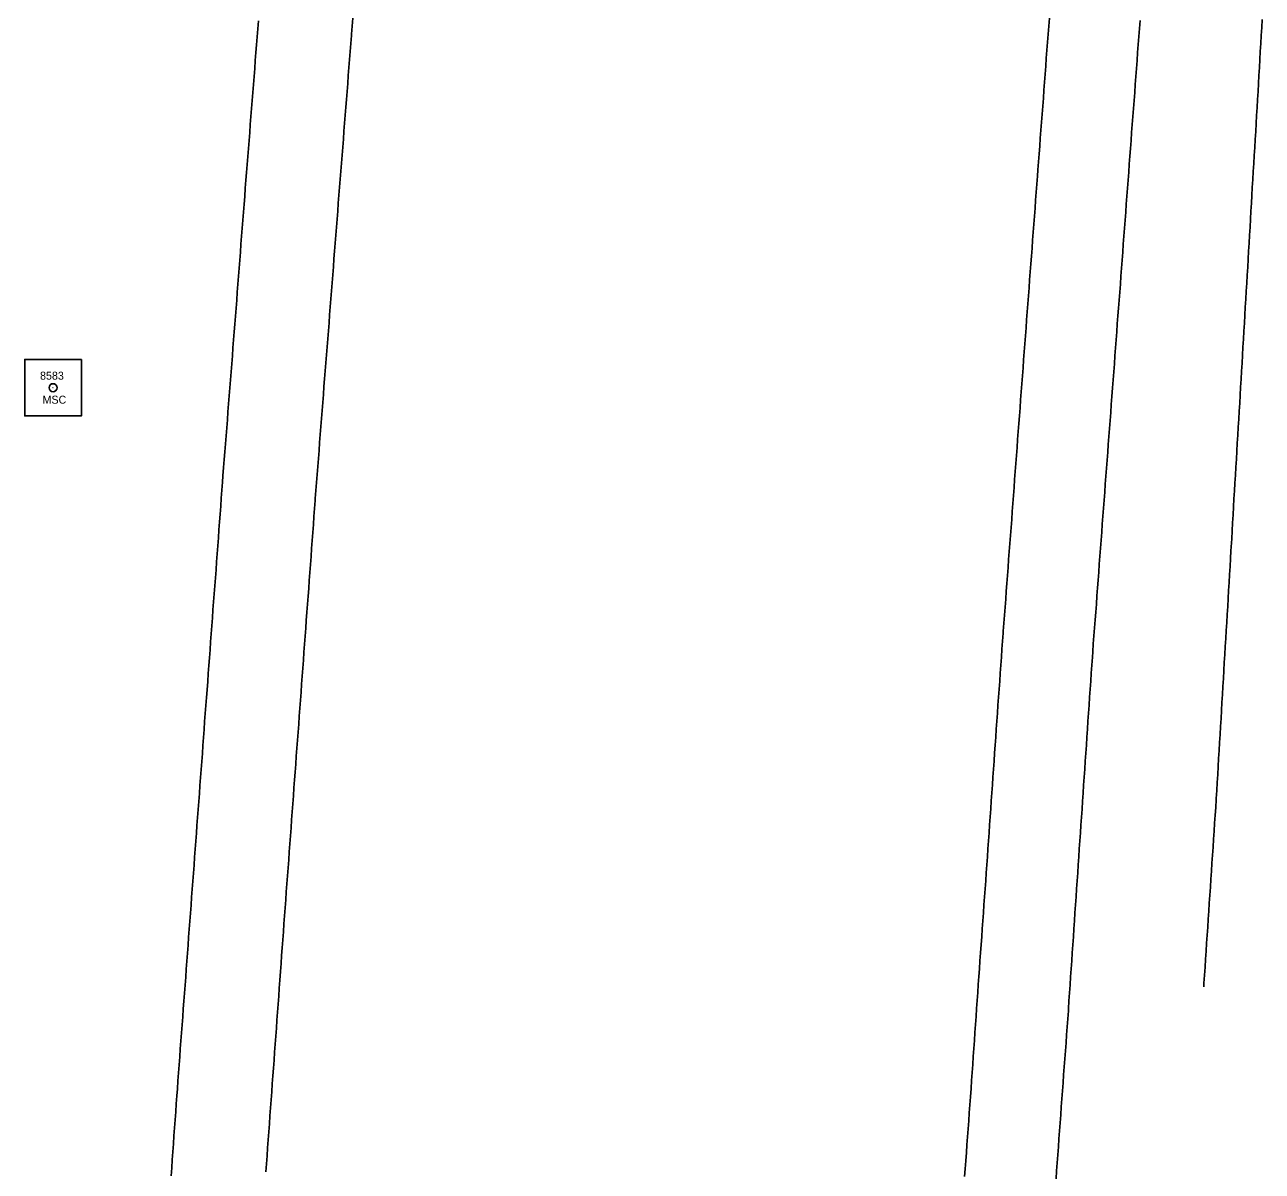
# Model space of a CAD drawing. Extents: x 205929 to 2357175, y -1785700 to 846739.
# Drawn here: x 2023347.6 to 2023502.2, y 808787.9 to 808931.1 of the extents above; entities that cross this region are included whole.
import ezdxf

# ---------------------------------------------------------------- set-up
doc = ezdxf.new("R2010")
doc.units = 0
for name, color, linetype in [('RD_HC_Survey', 7, 'Continuous'), ('RD_HC_txCode', 7, 'Continuous'), ('RD_Sketch1', 7, 'Continuous'), ('RD_SMD_Locator', 7, 'Continuous')]:
    doc.layers.add(name, color=color, linetype=linetype)

msp = doc.modelspace()

# ---------------------------------------------------------------- linework, layer by layer
at = {"layer": 'RD_HC_Survey'}
msp.add_lwpolyline([(2023354.64, 808889.34), (2023347.57, 808889.34), (2023347.57, 808882.27), (2023354.64, 808882.27)], close=True, dxfattribs=at)
msp.add_circle((2023351.11, 808885.8), 0.5, dxfattribs=at)
at = {"layer": 'RD_Sketch1'}
for points in [[(2023376.76, 808931.63), (2023376.68, 808930.64), (2023376.61, 808929.64), (2023376.53, 808928.64), (2023376.45, 808927.65), (2023376.37, 808926.65), (2023376.3, 808925.65), (2023376.22, 808924.65), (2023376.14, 808923.66), (2023376.06, 808922.66), (2023375.99, 808921.66), (2023375.91, 808920.67), (2023375.83, 808919.67), (2023375.75, 808918.67), (2023375.68, 808917.68), (2023375.6, 808916.68), (2023375.52, 808915.68), (2023375.44, 808914.69), (2023375.37, 808913.69), (2023375.29, 808912.69), (2023375.21, 808911.7), (2023375.13, 808910.7), (2023375.06, 808909.7), (2023375.06, 808909.7), (2023374.98, 808908.71), (2023374.9, 808907.71), (2023374.82, 808906.71), (2023374.75, 808905.71), (2023374.67, 808904.72), (2023374.59, 808903.72), (2023374.51, 808902.72), (2023374.44, 808901.73), (2023374.36, 808900.73), (2023374.28, 808899.73), (2023374.2, 808898.74), (2023374.13, 808897.74), (2023374.05, 808896.74), (2023373.97, 808895.75), (2023373.89, 808894.75), (2023373.82, 808893.75), (2023373.74, 808892.76), (2023373.66, 808891.76), (2023373.58, 808890.76), (2023373.51, 808889.77), (2023373.43, 808888.77), (2023373.35, 808887.77), (2023373.27, 808886.77), (2023373.2, 808885.78), (2023373.12, 808884.78), (2023373.04, 808883.78), (2023372.96, 808882.79), (2023372.89, 808881.79), (2023372.81, 808880.79), (2023372.73, 808879.8), (2023372.65, 808878.8), (2023372.58, 808877.8), (2023372.5, 808876.81), (2023372.42, 808875.81), (2023372.34, 808874.81), (2023372.28, 808874.01), (2023372.21, 808873.01), (2023372.13, 808872.02), (2023372.06, 808871.02), (2023371.98, 808870.02), (2023371.91, 808869.03), (2023371.84, 808868.03), (2023371.76, 808867.03), (2023371.69, 808866.03), (2023371.61, 808865.04), (2023371.54, 808864.04), (2023371.47, 808863.04), (2023371.39, 808862.05), (2023371.32, 808861.05), (2023371.24, 808860.05), (2023371.17, 808859.05), (2023371.09, 808858.06), (2023371.02, 808857.06), (2023370.95, 808856.06), (2023370.87, 808855.07), (2023370.8, 808854.07), (2023370.72, 808853.07), (2023370.65, 808852.07), (2023370.57, 808851.08), (2023370.5, 808850.08), (2023370.43, 808849.08), (2023370.35, 808848.08), (2023370.28, 808847.09), (2023370.2, 808846.09), (2023370.13, 808845.09), (2023370.05, 808844.1), (2023369.98, 808843.1), (2023369.91, 808842.1), (2023369.83, 808841.1), (2023369.76, 808840.11), (2023369.68, 808839.11), (2023369.61, 808838.11), (2023369.54, 808837.12), (2023369.46, 808836.12), (2023369.39, 808835.12), (2023369.31, 808834.12), (2023369.24, 808833.13), (2023369.16, 808832.13), (2023369.09, 808831.13), (2023369.02, 808830.14), (2023368.94, 808829.14), (2023368.87, 808828.14), (2023368.79, 808827.14), (2023368.72, 808826.15), (2023368.64, 808825.15), (2023368.57, 808824.15), (2023368.5, 808823.15), (2023368.42, 808822.16), (2023368.35, 808821.16), (2023368.27, 808820.16), (2023368.2, 808819.17), (2023368.12, 808818.17), (2023368.05, 808817.17), (2023367.98, 808816.17), (2023367.9, 808815.18), (2023367.83, 808814.18), (2023367.75, 808813.18), (2023367.68, 808812.19), (2023367.6, 808811.19), (2023367.53, 808810.19), (2023367.53, 808810.19), (2023367.46, 808809.19), (2023367.38, 808808.2), (2023367.31, 808807.2), (2023367.23, 808806.2), (2023367.16, 808805.21), (2023367.09, 808804.21), (2023367.01, 808803.21), (2023366.94, 808802.21), (2023366.86, 808801.22), (2023366.79, 808800.22), (2023366.71, 808799.22), (2023366.64, 808798.23), (2023366.57, 808797.33), (2023366.5, 808796.33), (2023366.43, 808795.33), (2023366.36, 808794.34), (2023366.29, 808793.34), (2023366.21, 808792.34), (2023366.14, 808791.34), (2023366.07, 808790.35), (2023366, 808789.35), (2023365.93, 808788.35), (2023365.85, 808787.35)], [(2023388.55, 808931.96), (2023388.48, 808930.96), (2023388.4, 808929.97), (2023388.39, 808929.79), (2023388.31, 808928.79), (2023388.23, 808927.79), (2023388.16, 808926.8), (2023388.08, 808925.8), (2023388, 808924.8), (2023387.92, 808923.81), (2023387.84, 808922.81), (2023387.77, 808921.81), (2023387.69, 808920.82), (2023387.61, 808919.82), (2023387.53, 808918.82), (2023387.46, 808917.83), (2023387.38, 808916.83), (2023387.3, 808915.83), (2023387.22, 808914.84), (2023387.14, 808913.84), (2023387.07, 808912.84), (2023386.99, 808911.85), (2023386.91, 808910.85), (2023386.83, 808909.85), (2023386.75, 808908.85), (2023386.75, 808908.85), (2023386.68, 808907.86), (2023386.6, 808906.86), (2023386.52, 808905.86), (2023386.44, 808904.87), (2023386.37, 808903.87), (2023386.29, 808902.87), (2023386.21, 808901.88), (2023386.13, 808900.88), (2023386.05, 808899.88), (2023385.98, 808898.89), (2023385.9, 808897.89), (2023385.82, 808896.89), (2023385.74, 808895.9), (2023385.66, 808894.9), (2023385.59, 808893.9), (2023385.51, 808892.91), (2023385.43, 808891.91), (2023385.35, 808890.91), (2023385.28, 808889.91), (2023385.2, 808888.92), (2023385.12, 808887.92), (2023385.04, 808886.92), (2023384.96, 808885.93), (2023384.89, 808884.93), (2023384.81, 808883.93), (2023384.73, 808882.94), (2023384.65, 808881.94), (2023384.57, 808880.94), (2023384.5, 808879.95), (2023384.42, 808878.95), (2023384.34, 808877.95), (2023384.26, 808876.96), (2023384.19, 808875.96), (2023384.11, 808874.96), (2023384.03, 808873.97), (2023383.95, 808872.97), (2023383.87, 808871.97), (2023383.85, 808871.7), (2023383.78, 808870.71), (2023383.71, 808869.71), (2023383.63, 808868.71), (2023383.56, 808867.71), (2023383.49, 808866.72), (2023383.41, 808865.72), (2023383.34, 808864.72), (2023383.27, 808863.72), (2023383.19, 808862.73), (2023383.12, 808861.73), (2023383.05, 808860.73), (2023382.97, 808859.74), (2023382.9, 808858.74), (2023382.83, 808857.74), (2023382.75, 808856.74), (2023382.68, 808855.75), (2023382.6, 808854.75), (2023382.53, 808853.75), (2023382.46, 808852.75), (2023382.38, 808851.76), (2023382.31, 808850.76), (2023382.24, 808849.76), (2023382.16, 808848.76), (2023382.09, 808847.77), (2023382.02, 808846.77), (2023381.94, 808845.77), (2023381.87, 808844.78), (2023381.8, 808843.78), (2023381.72, 808842.78), (2023381.65, 808841.78), (2023381.58, 808840.79), (2023381.5, 808839.79), (2023381.43, 808838.79), (2023381.36, 808837.79), (2023381.28, 808836.8), (2023381.21, 808835.8), (2023381.14, 808834.8), (2023381.06, 808833.81), (2023380.99, 808832.81), (2023380.92, 808831.81), (2023380.84, 808830.81), (2023380.77, 808829.82), (2023380.7, 808828.82), (2023380.62, 808827.82), (2023380.55, 808826.82), (2023380.47, 808825.83), (2023380.4, 808824.83), (2023380.33, 808823.83), (2023380.25, 808822.84), (2023380.18, 808821.84), (2023380.11, 808820.84), (2023380.03, 808819.84), (2023379.96, 808818.85), (2023379.89, 808817.85), (2023379.81, 808816.85), (2023379.74, 808815.85), (2023379.67, 808814.86), (2023379.59, 808813.86), (2023379.52, 808812.86), (2023379.44, 808811.79), (2023379.37, 808810.8), (2023379.3, 808809.8), (2023379.22, 808808.8), (2023379.15, 808807.8), (2023379.15, 808807.8), (2023379.08, 808806.81), (2023379.01, 808805.81), (2023378.94, 808804.81), (2023378.86, 808803.81), (2023378.79, 808802.82), (2023378.72, 808801.82), (2023378.65, 808800.82), (2023378.57, 808799.83), (2023378.5, 808798.83), (2023378.43, 808797.83), (2023378.36, 808796.83), (2023378.29, 808795.84), (2023378.21, 808794.84), (2023378.14, 808793.84), (2023378.07, 808792.84), (2023378, 808791.85), (2023377.92, 808790.85), (2023377.85, 808789.85), (2023377.78, 808788.86), (2023377.71, 808787.86)], [(2023475.6, 808931.94), (2023475.53, 808930.94), (2023475.45, 808929.94), (2023475.38, 808928.94), (2023475.3, 808927.95), (2023475.22, 808926.95), (2023475.15, 808925.95), (2023475.07, 808924.96), (2023475, 808923.96), (2023474.92, 808922.96), (2023474.85, 808921.97), (2023474.77, 808920.97), (2023474.7, 808919.97), (2023474.62, 808918.97), (2023474.54, 808917.98), (2023474.47, 808916.98), (2023474.39, 808915.98), (2023474.32, 808914.99), (2023474.24, 808913.99), (2023474.17, 808912.99), (2023474.11, 808912.22), (2023474.03, 808911.22), (2023473.96, 808910.22), (2023473.88, 808909.22), (2023473.81, 808908.23), (2023473.73, 808907.23), (2023473.66, 808906.23), (2023473.58, 808905.24), (2023473.51, 808904.24), (2023473.43, 808903.24), (2023473.36, 808902.24), (2023473.28, 808901.25), (2023473.21, 808900.25), (2023473.13, 808899.25), (2023473.06, 808898.26), (2023472.98, 808897.26), (2023472.91, 808896.26), (2023472.83, 808895.27), (2023472.76, 808894.27), (2023472.76, 808894.27), (2023472.68, 808893.27), (2023472.61, 808892.27), (2023472.53, 808891.28), (2023472.46, 808890.28), (2023472.38, 808889.28), (2023472.31, 808888.29), (2023472.23, 808887.29), (2023472.16, 808886.29), (2023472.08, 808885.29), (2023472.01, 808884.3), (2023471.93, 808883.3), (2023471.86, 808882.3), (2023471.78, 808881.31), (2023471.71, 808880.31), (2023471.63, 808879.31), (2023471.56, 808878.31), (2023471.49, 808877.32), (2023471.41, 808876.32), (2023471.34, 808875.32), (2023471.26, 808874.33), (2023471.19, 808873.33), (2023471.11, 808872.33), (2023471.04, 808871.33), (2023470.96, 808870.34), (2023470.89, 808869.34), (2023470.81, 808868.34), (2023470.74, 808867.35), (2023470.66, 808866.35), (2023470.59, 808865.35), (2023470.51, 808864.35), (2023470.44, 808863.36), (2023470.36, 808862.36), (2023470.29, 808861.36), (2023470.21, 808860.37), (2023470.14, 808859.37), (2023470.06, 808858.37), (2023469.99, 808857.37), (2023469.91, 808856.38), (2023469.84, 808855.38), (2023469.82, 808855.13), (2023469.75, 808854.13), (2023469.68, 808853.13), (2023469.61, 808852.14), (2023469.54, 808851.14), (2023469.47, 808850.14), (2023469.4, 808849.14), (2023469.33, 808848.15), (2023469.26, 808847.15), (2023469.18, 808846.15), (2023469.11, 808845.15), (2023469.04, 808844.16), (2023468.97, 808843.16), (2023468.9, 808842.16), (2023468.83, 808841.16), (2023468.76, 808840.17), (2023468.69, 808839.17), (2023468.62, 808838.17), (2023468.55, 808837.17), (2023468.48, 808836.18), (2023468.41, 808835.18), (2023468.34, 808834.18), (2023468.27, 808833.18), (2023468.2, 808832.19), (2023468.13, 808831.19), (2023468.06, 808830.19), (2023467.99, 808829.19), (2023467.92, 808828.2), (2023467.85, 808827.2), (2023467.78, 808826.2), (2023467.71, 808825.2), (2023467.64, 808824.21), (2023467.57, 808823.21), (2023467.5, 808822.21), (2023467.43, 808821.21), (2023467.36, 808820.22), (2023467.29, 808819.22), (2023467.22, 808818.22), (2023467.15, 808817.22), (2023467.08, 808816.23), (2023467.01, 808815.23), (2023466.93, 808814.23), (2023466.86, 808813.23), (2023466.79, 808812.24), (2023466.72, 808811.24), (2023466.65, 808810.24), (2023466.58, 808809.24), (2023466.51, 808808.25), (2023466.44, 808807.25), (2023466.37, 808806.25), (2023466.3, 808805.25), (2023466.23, 808804.26), (2023466.16, 808803.26), (2023466.09, 808802.26), (2023466.02, 808801.26), (2023465.95, 808800.27), (2023465.88, 808799.27), (2023465.81, 808798.27), (2023465.74, 808797.23), (2023465.66, 808796.23), (2023465.59, 808795.23), (2023465.52, 808794.24), (2023465.45, 808793.24), (2023465.37, 808792.24), (2023465.3, 808791.24), (2023465.3, 808791.24), (2023465.23, 808790.25), (2023465.15, 808789.25), (2023465.08, 808788.25), (2023465.01, 808787.26)], [(2023486.93, 808931.65), (2023486.86, 808930.65), (2023486.78, 808929.65), (2023486.71, 808928.66), (2023486.63, 808927.66), (2023486.56, 808926.66), (2023486.48, 808925.66), (2023486.41, 808924.67), (2023486.33, 808923.67), (2023486.26, 808922.67), (2023486.18, 808921.68), (2023486.11, 808920.68), (2023486.03, 808919.68), (2023485.96, 808918.69), (2023485.88, 808917.69), (2023485.81, 808916.69), (2023485.74, 808915.69), (2023485.66, 808914.7), (2023485.59, 808913.7), (2023485.51, 808912.7), (2023485.44, 808911.71), (2023485.36, 808910.71), (2023485.29, 808909.71), (2023485.21, 808908.71), (2023485.14, 808907.72), (2023485.06, 808906.72), (2023484.99, 808905.72), (2023484.91, 808904.73), (2023484.84, 808903.73), (2023484.76, 808902.73), (2023484.69, 808901.74), (2023484.61, 808900.74), (2023484.54, 808899.74), (2023484.47, 808898.74), (2023484.39, 808897.75), (2023484.32, 808896.75), (2023484.24, 808895.75), (2023484.17, 808894.76), (2023484.09, 808893.76), (2023484.02, 808892.76), (2023484.02, 808892.76), (2023483.94, 808891.76), (2023483.87, 808890.77), (2023483.79, 808889.77), (2023483.72, 808888.77), (2023483.64, 808887.78), (2023483.57, 808886.78), (2023483.49, 808885.78), (2023483.41, 808884.71), (2023483.34, 808883.71), (2023483.26, 808882.71), (2023483.19, 808881.72), (2023483.11, 808880.72), (2023483.04, 808879.72), (2023482.96, 808878.72), (2023482.89, 808877.73), (2023482.81, 808876.73), (2023482.74, 808875.73), (2023482.66, 808874.74), (2023482.59, 808873.74), (2023482.51, 808872.74), (2023482.44, 808871.74), (2023482.36, 808870.75), (2023482.29, 808869.75), (2023482.21, 808868.75), (2023482.14, 808867.76), (2023482.06, 808866.76), (2023481.99, 808865.76), (2023481.92, 808864.76), (2023481.84, 808863.77), (2023481.77, 808862.77), (2023481.69, 808861.77), (2023481.62, 808860.78), (2023481.54, 808859.78), (2023481.47, 808858.78), (2023481.39, 808857.78), (2023481.32, 808856.79), (2023481.24, 808855.79), (2023481.17, 808854.79), (2023481.09, 808853.8), (2023481.02, 808852.8), (2023480.97, 808852.12), (2023480.9, 808851.13), (2023480.83, 808850.13), (2023480.76, 808849.13), (2023480.69, 808848.13), (2023480.63, 808847.14), (2023480.56, 808846.14), (2023480.49, 808845.14), (2023480.42, 808844.14), (2023480.36, 808843.15), (2023480.29, 808842.15), (2023480.22, 808841.15), (2023480.15, 808840.15), (2023480.09, 808839.16), (2023480.02, 808838.16), (2023479.95, 808837.16), (2023479.88, 808836.16), (2023479.81, 808835.16), (2023479.75, 808834.17), (2023479.68, 808833.17), (2023479.61, 808832.17), (2023479.54, 808831.17), (2023479.48, 808830.18), (2023479.41, 808829.18), (2023479.34, 808828.18), (2023479.27, 808827.18), (2023479.2, 808826.19), (2023479.14, 808825.19), (2023479.07, 808824.19), (2023479, 808823.19), (2023478.93, 808822.19), (2023478.87, 808821.2), (2023478.8, 808820.2), (2023478.73, 808819.2), (2023478.66, 808818.2), (2023478.6, 808817.21), (2023478.53, 808816.21), (2023478.46, 808815.21), (2023478.39, 808814.21), (2023478.32, 808813.22), (2023478.26, 808812.22), (2023478.19, 808811.22), (2023478.12, 808810.22), (2023478.05, 808809.23), (2023477.99, 808808.23), (2023477.97, 808807.95), (2023477.89, 808806.95), (2023477.82, 808805.95), (2023477.75, 808804.96), (2023477.68, 808803.96), (2023477.6, 808802.96), (2023477.53, 808801.96), (2023477.46, 808800.97), (2023477.38, 808799.97), (2023477.31, 808798.97), (2023477.24, 808797.98), (2023477.16, 808796.98), (2023477.09, 808795.98), (2023477.02, 808794.98), (2023476.94, 808793.99), (2023476.87, 808792.99), (2023476.8, 808791.99), (2023476.73, 808790.99), (2023476.65, 808790), (2023476.58, 808789), (2023476.58, 808789), (2023476.51, 808788), (2023476.43, 808787)], [(2023502.2, 808931.78), (2023502.14, 808930.79), (2023502.08, 808929.79), (2023502.02, 808928.79), (2023501.96, 808927.79), (2023501.91, 808926.79), (2023501.85, 808925.79), (2023501.79, 808924.8), (2023501.73, 808923.8), (2023501.67, 808922.8), (2023501.61, 808921.8), (2023501.55, 808920.8), (2023501.49, 808919.81), (2023501.44, 808918.81), (2023501.38, 808917.81), (2023501.32, 808916.81), (2023501.26, 808915.81), (2023501.2, 808914.82), (2023501.14, 808913.82), (2023501.08, 808912.82), (2023501.02, 808911.82), (2023500.96, 808910.82), (2023500.91, 808909.82), (2023500.85, 808908.83), (2023500.79, 808907.83), (2023500.73, 808906.83), (2023500.73, 808906.83), (2023500.67, 808905.83), (2023500.61, 808904.83), (2023500.55, 808903.84), (2023500.49, 808902.84), (2023500.44, 808901.84), (2023500.38, 808900.84), (2023500.32, 808899.84), (2023500.26, 808898.85), (2023500.2, 808897.85), (2023500.14, 808896.85), (2023500.08, 808895.85), (2023500.02, 808894.85), (2023499.97, 808893.86), (2023499.91, 808892.86), (2023499.85, 808891.86), (2023499.79, 808890.86), (2023499.73, 808889.86), (2023499.67, 808888.86), (2023499.61, 808887.87), (2023499.55, 808886.87), (2023499.5, 808885.87), (2023499.44, 808884.87), (2023499.38, 808883.87), (2023499.32, 808882.88), (2023499.26, 808881.88), (2023499.2, 808880.88), (2023499.14, 808879.88), (2023499.08, 808878.88), (2023499.03, 808877.89), (2023498.97, 808876.89), (2023498.91, 808875.89), (2023498.85, 808874.89), (2023498.79, 808873.89), (2023498.73, 808872.9), (2023498.67, 808871.9), (2023498.61, 808870.9), (2023498.56, 808869.9), (2023498.5, 808868.9), (2023498.44, 808867.9), (2023498.38, 808866.91), (2023498.32, 808865.91), (2023498.29, 808865.44), (2023498.23, 808864.45), (2023498.18, 808863.45), (2023498.12, 808862.45), (2023498.06, 808861.45), (2023498, 808860.45), (2023497.94, 808859.45), (2023497.88, 808858.46), (2023497.82, 808857.46), (2023497.76, 808856.46), (2023497.7, 808855.46), (2023497.64, 808854.46), (2023497.58, 808853.47), (2023497.52, 808852.47), (2023497.46, 808851.47), (2023497.41, 808850.47), (2023497.35, 808849.47), (2023497.29, 808848.47), (2023497.23, 808847.48), (2023497.17, 808846.48), (2023497.11, 808845.48), (2023497.05, 808844.48), (2023496.99, 808843.48), (2023496.93, 808842.48), (2023496.87, 808841.49), (2023496.81, 808840.49), (2023496.75, 808839.49), (2023496.69, 808838.49), (2023496.64, 808837.49), (2023496.58, 808836.5), (2023496.52, 808835.5), (2023496.46, 808834.5), (2023496.45, 808834.38), (2023496.38, 808833.38), (2023496.32, 808832.39), (2023496.25, 808831.39), (2023496.18, 808830.39), (2023496.12, 808829.39), (2023496.05, 808828.4), (2023495.98, 808827.4), (2023495.92, 808826.4), (2023495.85, 808825.4), (2023495.78, 808824.4), (2023495.72, 808823.41), (2023495.65, 808822.41), (2023495.58, 808821.41), (2023495.52, 808820.41), (2023495.45, 808819.42), (2023495.38, 808818.42), (2023495.32, 808817.42), (2023495.25, 808816.42), (2023495.18, 808815.43), (2023495.12, 808814.43), (2023495.05, 808813.43), (2023494.98, 808812.43), (2023494.92, 808811.43), (2023494.88, 808810.97)]]:
    msp.add_lwpolyline(points, dxfattribs=at)
at = {"layer": 'RD_SMD_Locator'}
msp.add_circle((2023351.11, 808885.8), 0.001, dxfattribs=at)

# ---------------------------------------------------------------- texts
at = {"layer": 'RD_HC_txCode'}
for s, p in [('8583', (2023349.48, 808886.8)), ('MSC', (2023349.79, 808883.8))]:
    msp.add_text(s, height=1, dxfattribs=at).set_placement(p)

doc.saveas('drawing.dxf')
